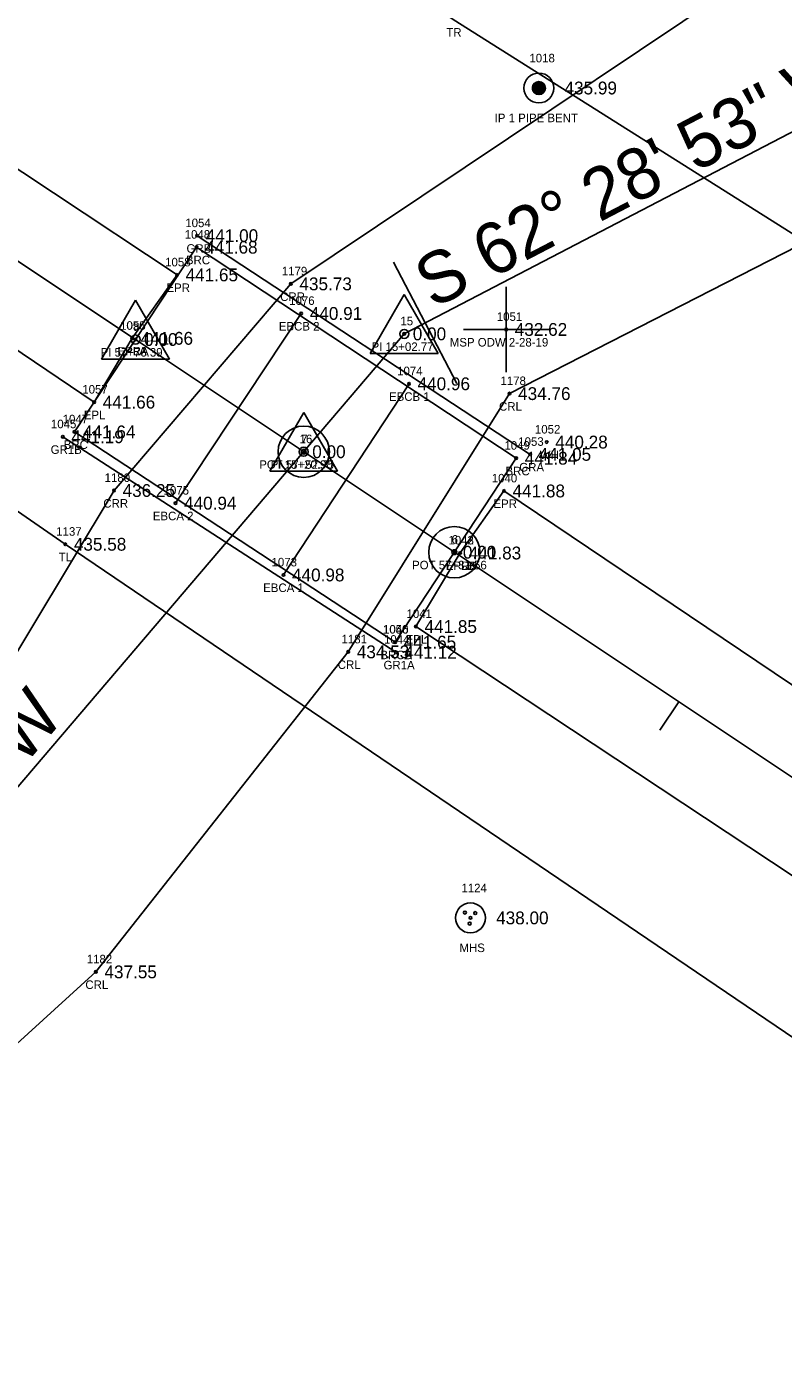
# Model space of a CAD drawing. Extents: x 1796360 to 1799195, y 895805 to 899730.
# Drawn here: x 1798350 to 1798438.5, y 896378.1 to 896534.1 of the extents above; entities that cross this region are included whole.
import ezdxf

# ---------------------------------------------------------------- set-up
doc = ezdxf.new("R2010")
doc.units = 0
for name, color, linetype in [('RD_EX_Bridge', 7, 'Continuous'), ('RD_EX_Bridge_txCode', 7, 'Continuous'), ('RD_EX_DR_Inlet', 7, 'Continuous'), ('RD_EX_DV_Prop_txCode', 7, 'Continuous'), ('RD_EX_DV_PropPin', 7, 'Continuous'), ('RD_EX_GuardRail', 7, 'Continuous'), ('RD_EX_GuardRail_txCode', 7, 'Continuous'), ('RD_EX_H2O', 7, 'Continuous'), ('RD_EX_H2O_txCode', 7, 'Continuous'), ('RD_EX_Misc_txCode', 7, 'Continuous'), ('RD_EX_Road', 7, 'Continuous'), ('RD_EX_Road_txCode', 7, 'Continuous'), ('RD_EX_SU_Misc_TxCode', 7, 'Continuous'), ('RD_EX_TX_Bridge_ELEV', 7, 'Continuous'), ('RD_EX_TX_DV_Prop_ELEV', 7, 'Continuous'), ('RD_EX_TX_GuardRail_ELEV', 7, 'Continuous'), ('RD_EX_TX_H2O_ELEV', 7, 'Continuous'), ('RD_EX_TX_Misc_ELEV', 7, 'Continuous'), ('RD_EX_TX_Road_ELEV', 7, 'Continuous'), ('RD_EX_TX_UT_ELEV', 7, 'Continuous'), ('RD_EX_TX_VEG_ELEV', 7, 'Continuous'), ('RD_EX_UT_txCode', 7, 'Continuous'), ('RD_EX_VEG', 7, 'Continuous'), ('RD_EX_VEG_txCode', 7, 'Continuous'), ('RD_HC_Cl', 7, 'Continuous'), ('RD_HC_Data', 7, 'Continuous'), ('RD_HC_Data_Tic', 7, 'Continuous'), ('RD_HC_Survey_ELEV', 7, 'Continuous'), ('RD_HC_txCode', 7, 'Continuous'), ('RD_SMD_Locator', 7, 'Continuous')]:
    doc.layers.add(name, color=color, linetype=linetype)

msp = doc.modelspace()

# ---------------------------------------------------------------- linework, layer by layer
at = {"layer": 'RD_EX_Bridge'}
for p, q in [((1798367.36, 896478.36), (1798382.07, 896500.56)), ((1798379.99, 896469.96), (1798394.68, 896492.33))]:
    msp.add_line(p, q, dxfattribs=at)
msp.add_lwpolyline([(1798393.06, 896462.1), (1798355.54, 896486.7), (1798369.83, 896508.31), (1798407.22, 896483.62), (1798393.06, 896462.1)], dxfattribs=at)
at = {"layer": 'RD_EX_DR_Inlet'}
for centre, radius in [((1798401.87, 896429.83), 1.75), ((1798401.21, 896430.46), 0.175), ((1798402.43, 896430.39), 0.175), ((1798401.78, 896429.17), 0.175)]:
    msp.add_circle(centre, radius, dxfattribs=at)
at = {"layer": 'RD_EX_DV_PropPin'}
for p, q in [((1798409.2, 896526.57), (1798409.2, 896527.31)), ((1798409.23, 896526.51), (1798409.23, 896527.36)), ((1798409.27, 896526.46), (1798409.27, 896527.41)), ((1798409.3, 896526.42), (1798409.3, 896527.45)), ((1798409.34, 896526.39), (1798409.34, 896527.49)), ((1798409.37, 896526.36), (1798409.37, 896527.52)), ((1798409.41, 896526.33), (1798409.41, 896527.55)), ((1798409.44, 896526.3), (1798409.44, 896527.57)), ((1798409.48, 896526.28), (1798409.48, 896527.59)), ((1798409.51, 896526.26), (1798409.51, 896527.61)), ((1798409.55, 896526.25), (1798409.55, 896527.63)), ((1798409.58, 896526.23), (1798409.58, 896527.65)), ((1798409.62, 896526.22), (1798409.62, 896527.66)), ((1798409.65, 896526.21), (1798409.65, 896527.67)), ((1798409.69, 896526.2), (1798409.69, 896527.68)), ((1798409.73, 896526.19), (1798409.73, 896527.69)), ((1798409.76, 896526.18), (1798409.76, 896527.69)), ((1798409.8, 896526.18), (1798409.8, 896527.7)), ((1798409.83, 896526.18), (1798409.83, 896527.7)), ((1798409.87, 896526.18), (1798409.87, 896527.7)), ((1798409.9, 896526.18), (1798409.9, 896527.7)), ((1798409.94, 896526.18), (1798409.94, 896527.7)), ((1798409.97, 896526.18), (1798409.97, 896527.69)), ((1798410.01, 896526.19), (1798410.01, 896527.69)), ((1798410.04, 896526.2), (1798410.04, 896527.68)), ((1798410.08, 896526.21), (1798410.08, 896527.67)), ((1798410.11, 896526.22), (1798410.11, 896527.66)), ((1798410.15, 896526.23), (1798410.15, 896527.65)), ((1798410.18, 896526.25), (1798410.18, 896527.63)), ((1798410.22, 896526.26), (1798410.22, 896527.61)), ((1798410.25, 896526.28), (1798410.25, 896527.59)), ((1798410.29, 896526.3), (1798410.29, 896527.57)), ((1798410.32, 896526.33), (1798410.32, 896527.55)), ((1798410.36, 896526.36), (1798410.36, 896527.52)), ((1798410.39, 896526.39), (1798410.39, 896527.49)), ((1798410.43, 896526.42), (1798410.43, 896527.45)), ((1798410.46, 896526.46), (1798410.46, 896527.41)), ((1798410.5, 896526.51), (1798410.5, 896527.36)), ((1798410.53, 896526.57), (1798410.53, 896527.31)), ((1798409.13, 896526.74), (1798409.13, 896527.13)), ((1798409.16, 896526.64), (1798409.16, 896527.24)), ((1798410.57, 896526.64), (1798410.57, 896527.24)), ((1798410.6, 896526.74), (1798410.6, 896527.13))]:
    msp.add_line(p, q, dxfattribs=at)
for radius in [1.75, 0.761]:
    msp.add_circle((1798409.87, 896526.94), radius, dxfattribs=at)
at = {"layer": 'RD_EX_GuardRail'}
for p, q in [((1798408.85, 896484.07), (1798369.9, 896509.66)), ((1798393.13, 896460.91), (1798354.18, 896486.13))]:
    msp.add_line(p, q, dxfattribs=at)
at = {"layer": 'RD_EX_H2O'}
for p, q in [((1798406.05, 896493.69), (1798406.05, 896503.69)), ((1798401.05, 896498.69), (1798411.05, 896498.69))]:
    msp.add_line(p, q, dxfattribs=at)
for points in [[(1798502.61, 896635.66), (1798452.16, 896551.79), (1798380.86, 896504.02), (1798360.17, 896479.84), (1798335.44, 896438.68), (1798277.37, 896387.2), (1798228.36, 896339.61), (1798175.66, 896278.7), (1798083.83, 896204.11), (1798020.11, 896146.19)], [(1798443.56, 896510.19), (1798406.44, 896491.18), (1798387.57, 896460.96), (1798358.05, 896423.51), (1798298.17, 896368.97), (1798249.86, 896318.72)]]:
    msp.add_lwpolyline(points, dxfattribs=at)
msp.add_circle((1798406.05, 896498.69), 0.15, dxfattribs=at)
at = {"layer": 'RD_EX_Road'}
for points in [[(1798362.28, 896497.65), (1798367.54, 896505.07), (1798280.71, 896562.69), (1798193.2, 896621.02), (1798104.98, 896679.23), (1798017.88, 896737.39), (1797930.72, 896795.63), (1797844.07, 896853.07), (1797758.11, 896906.97)], [(1798362.28, 896497.65), (1798357.85, 896490.18), (1798271.29, 896548.71), (1798183.2, 896606.17), (1798096.06, 896663.44), (1798006.57, 896721.75), (1797920.8, 896779.27), (1797834.41, 896836.87), (1797748.77, 896891.01)], [(1799016.83, 896078.37), (1798931.94, 896134.3), (1798843.73, 896191.67), (1798753.3, 896249.87), (1798664.51, 896307.9), (1798573.47, 896367.69), (1798486.82, 896425.22), (1798405.79, 896479.79), (1798400.67, 896472.53)], [(1799005.77, 896063.27), (1798987.67, 896075.09), (1798974.89, 896083.47), (1798920.67, 896119.42), (1798834.47, 896175.11), (1798832.16, 896176.64), (1798822.63, 896182.83), (1798742.86, 896234.39), (1798653.4, 896292.37), (1798563.64, 896351.71), (1798476.02, 896410.61), (1798395.49, 896463.92), (1798400.67, 896472.53)]]:
    msp.add_lwpolyline(points, dxfattribs=at)
at = {"layer": 'RD_EX_SU_Misc_TxCode'}
msp.add_circle((1798410.79, 896485.51), 0.15, dxfattribs=at)
at = {"layer": 'RD_EX_VEG'}
for points in [[(1799022.27, 896088.33), (1798937.86, 896144.41), (1798896.41, 896211.5), (1798869.11, 896228.04), (1798778.26, 896284.04), (1798691.36, 896345.52), (1798595.8, 896403.96), (1798518.88, 896459.81), (1798399.83, 896534.95), (1798299.84, 896602.99), (1798218.96, 896659.85), (1798132.31, 896718.94), (1798044.28, 896770.93), (1797952.52, 896827.83), (1797861.07, 896893.41), (1797773.58, 896947.34)], [(1798749.58, 896161.12), (1798777.44, 896196.37), (1798732.29, 896222.81), (1798646.22, 896279.46), (1798558.62, 896342.53), (1798466.43, 896397.6), (1798354.47, 896473.55), (1798259.03, 896539.65), (1798173.88, 896596.34), (1798087.56, 896652.32), (1797997.75, 896711.89), (1797914.4, 896770.94), (1797832.15, 896824.19), (1797742.8, 896880.21)]]:
    msp.add_lwpolyline(points, dxfattribs=at)
at = {"layer": 'RD_HC_Cl'}
for p, q in [((1798362.69, 896497.51), (1798188.2, 896613.6)), ((1798452.47, 896528.57), (1798394.12, 896498.17)), ((1798394.12, 896498.17), (1798280.52, 896365)), ((1798659.28, 896299.6), (1798362.69, 896497.51))]:
    msp.add_line(p, q, dxfattribs=at)
at = {"layer": 'RD_HC_Data'}
for p, q in [((1798390.15, 896495.88), (1798394.12, 896502.76)), ((1798394.12, 896502.76), (1798398.09, 896495.88)), ((1798358.71, 896495.22), (1798362.69, 896502.1)), ((1798362.69, 896502.1), (1798366.66, 896495.22)), ((1798358.71, 896495.22), (1798366.66, 896495.22)), ((1798390.15, 896495.88), (1798398.09, 896495.88)), ((1798378.39, 896482.09), (1798382.36, 896488.97)), ((1798382.36, 896488.97), (1798386.33, 896482.09)), ((1798378.39, 896482.09), (1798386.33, 896482.09))]:
    msp.add_line(p, q, dxfattribs=at)
for centre, radius in [((1798362.69, 896497.51), 0.529), ((1798394.12, 896498.17), 0.529), ((1798382.36, 896484.38), 3), ((1798382.36, 896484.38), 0.529), ((1798382.36, 896484.38), 0.282), ((1798399.98, 896472.62), 3), ((1798399.98, 896472.62), 0.282)]:
    msp.add_circle(centre, radius, dxfattribs=at)
at = {"layer": 'RD_HC_Data_Tic'}
for p, q in [((1798396.58, 896499.45), (1798392.88, 896506.55)), ((1798396.58, 896499.45), (1798400.27, 896492.36)), ((1798426.23, 896455.11), (1798424.01, 896451.78))]:
    msp.add_line(p, q, dxfattribs=at)
at = {"layer": 'RD_SMD_Locator'}
for centre in [(1798409.87, 896526.94), (1798369.9, 896509.66), (1798369.83, 896508.31), (1798367.54, 896505.07), (1798380.86, 896504.02), (1798382.07, 896500.56), (1798362.28, 896497.65), (1798362.28, 896497.65), (1798362.69, 896497.51), (1798394.12, 896498.17), (1798394.68, 896492.33), (1798357.85, 896490.18), (1798406.44, 896491.18), (1798355.54, 896486.7), (1798354.18, 896486.13), (1798382.36, 896484.38), (1798382.36, 896484.38), (1798407.22, 896483.62), (1798408.85, 896484.07), (1798360.17, 896479.84), (1798405.79, 896479.79), (1798367.36, 896478.36), (1798354.47, 896473.55), (1798399.98, 896472.62), (1798400.67, 896472.53), (1798400.67, 896472.53), (1798379.99, 896469.96), (1798395.49, 896463.92), (1798393.06, 896462.1), (1798393.06, 896462.1), (1798387.57, 896460.96), (1798393.13, 896460.91), (1798401.87, 896429.83), (1798358.05, 896423.51)]:
    msp.add_circle(centre, 0.15, dxfattribs=at)

# ---------------------------------------------------------------- texts
at = {"layer": 'RD_EX_Bridge_txCode'}
for s, p in [('1048', (1798368.44, 896509.31)), ('BRC', (1798368.58, 896506.31)), ('1076', (1798380.66, 896501.56)), ('EBCB 2', (1798379.45, 896498.56)), ('1074', (1798393.29, 896493.33)), ('EBCB 1', (1798392.34, 896490.33)), ('1047', (1798354.16, 896487.7)), ('BRC', (1798354.29, 896484.7)), ('1049', (1798405.84, 896484.62)), ('BRC', (1798405.97, 896481.62)), ('1075', (1798365.97, 896479.36)), ('EBCA 2', (1798364.71, 896476.36)), ('1073', (1798378.6, 896470.96)), ('EBCA 1', (1798377.62, 896467.96)), ('1050', (1798391.63, 896463.1)), ('1046', (1798391.65, 896463.1)), ('BRCA', (1798391.32, 896460.1)), ('BRCB', (1798391.33, 896460.1))]:
    msp.add_text(s, height=1, dxfattribs=at).set_placement(p)
at = {"layer": 'RD_EX_DV_Prop_txCode'}
for s, p in [('1018', (1798408.76, 896529.94)), ('IP 1 PIPE BENT', (1798404.7, 896522.94))]:
    msp.add_text(s, height=1, dxfattribs=at).set_placement(p)
at = {"layer": 'RD_EX_GuardRail_txCode'}
for s, p in [('1054', (1798368.51, 896510.66)), ('GRB', (1798368.65, 896507.66)), ('1045', (1798352.79, 896487.13)), ('GR1B', (1798352.76, 896484.13)), ('1053', (1798407.46, 896485.07)), ('GRA', (1798407.58, 896482.07)), ('1044', (1798391.75, 896461.91)), ('GR1A', (1798391.7, 896458.91))]:
    msp.add_text(s, height=1, dxfattribs=at).set_placement(p)
at = {"layer": 'RD_EX_H2O_txCode'}
for s, p in [('1179', (1798379.8, 896505.02)), ('CRR', (1798379.61, 896502.02)), ('1178', (1798405.38, 896492.18)), ('CRL', (1798405.21, 896489.18)), ('1180', (1798359.07, 896480.84)), ('CRR', (1798358.92, 896477.84)), ('1181', (1798386.79, 896461.96)), ('CRL', (1798386.34, 896458.96)), ('1182', (1798356.98, 896424.51)), ('CRL', (1798356.82, 896421.51))]:
    msp.add_text(s, height=1, dxfattribs=at).set_placement(p)
at = {"layer": 'RD_EX_Misc_txCode'}
for s, p in [('1051', (1798404.95, 896499.69)), ('MSP ODW 2-28-19', (1798399.45, 896496.69)), ('1052', (1798409.41, 896486.51)), ('WH', (1798409.98, 896483.51))]:
    msp.add_text(s, height=1, dxfattribs=at).set_placement(p)
at = {"layer": 'RD_EX_Road_txCode'}
for s, p in [('1058', (1798366.15, 896506.07)), ('EPR', (1798366.31, 896503.07)), ('1056', (1798360.87, 896498.65)), ('1055', (1798360.9, 896498.65)), ('EPRA', (1798360.57, 896495.65)), ('EPLA', (1798360.59, 896495.65)), ('1057', (1798356.46, 896491.18)), ('EPL', (1798356.64, 896488.18)), ('1040', (1798404.36, 896480.79)), ('EPR', (1798404.56, 896477.79)), ('1042', (1798399.29, 896473.53)), ('1043', (1798399.29, 896473.53)), ('EPRB', (1798398.97, 896470.53)), ('EPLB', (1798398.99, 896470.53)), ('1041', (1798394.39, 896464.92)), ('EPL', (1798394.28, 896461.92))]:
    msp.add_text(s, height=1, dxfattribs=at).set_placement(p)
at = {"layer": 'RD_EX_TX_Bridge_ELEV'}
for s, p in [('441.68', (1798370.83, 896507.56)), ('440.91', (1798383.07, 896499.81)), ('440.96', (1798395.68, 896491.58)), ('441.64', (1798356.54, 896485.95)), ('441.84', (1798408.22, 896482.87)), ('440.94', (1798368.36, 896477.61)), ('440.98', (1798380.99, 896469.21)), ('441.65', (1798394.06, 896461.35)), ('441.65', (1798394.06, 896461.35))]:
    msp.add_text(s, height=1.5, dxfattribs=at).set_placement(p)
at = {"layer": 'RD_EX_TX_DV_Prop_ELEV'}
msp.add_text('435.99', height=1.5, dxfattribs=at).set_placement((1798412.87, 896526.19))
at = {"layer": 'RD_EX_TX_GuardRail_ELEV'}
for s, p in [('441.00', (1798370.9, 896508.91)), ('441.19', (1798355.18, 896485.38)), ('441.05', (1798409.85, 896483.32)), ('441.12', (1798394.13, 896460.16))]:
    msp.add_text(s, height=1.5, dxfattribs=at).set_placement(p)
at = {"layer": 'RD_EX_TX_H2O_ELEV'}
for s, p in [('435.73', (1798381.86, 896503.27)), ('434.76', (1798407.44, 896490.43)), ('436.25', (1798361.17, 896479.09)), ('434.53', (1798388.57, 896460.21)), ('437.55', (1798359.05, 896422.76))]:
    msp.add_text(s, height=1.5, dxfattribs=at).set_placement(p)
at = {"layer": 'RD_EX_TX_Misc_ELEV'}
for s, p in [('432.62', (1798407.05, 896497.94)), ('440.28', (1798411.79, 896484.76))]:
    msp.add_text(s, height=1.5, dxfattribs=at).set_placement(p)
at = {"layer": 'RD_EX_TX_Road_ELEV'}
for s, p in [('441.65', (1798368.54, 896504.32)), ('441.66', (1798363.28, 896496.9)), ('441.66', (1798363.28, 896496.9)), ('441.66', (1798358.85, 896489.43)), ('441.88', (1798406.79, 896479.04)), ('441.83', (1798401.67, 896471.78)), ('441.83', (1798401.67, 896471.78)), ('441.85', (1798396.49, 896463.17))]:
    msp.add_text(s, height=1.5, dxfattribs=at).set_placement(p)
at = {"layer": 'RD_EX_TX_UT_ELEV'}
msp.add_text('438.00', height=1.5, dxfattribs=at).set_placement((1798404.87, 896429.08))
at = {"layer": 'RD_EX_TX_VEG_ELEV'}
msp.add_text('435.58', height=1.5, dxfattribs=at).set_placement((1798355.47, 896472.8))
at = {"layer": 'RD_EX_UT_txCode'}
for s, p in [('1124', (1798400.81, 896432.83)), ('MHS', (1798400.58, 896425.83))]:
    msp.add_text(s, height=1, dxfattribs=at).set_placement(p)
at = {"layer": 'RD_EX_VEG_txCode'}
for s, p in [('TR', (1798399.04, 896532.95)), ('1137', (1798353.41, 896474.55)), ('TL', (1798353.7, 896471.55))]:
    msp.add_text(s, height=1, dxfattribs=at).set_placement(p)
at = {"layer": 'RD_HC_Data'}
for s, rotation, p in [('S 62%%d 28\' 53" W', 27.5186, (1798397.48, 896501.05)), ('S 40%%d 27\' 57" W', 49.5342, (1798318.01, 896410.49))]:
    msp.add_text(s, height=6, rotation=rotation, dxfattribs=at).set_placement(p)
at = {"layer": 'RD_HC_Survey_ELEV'}
for p in [(1798363.69, 896496.76), (1798395.12, 896497.42), (1798383.36, 896483.63), (1798383.36, 896483.63), (1798400.98, 896471.87)]:
    msp.add_text('0.00', height=1.5, dxfattribs=at).set_placement(p)
at = {"layer": 'RD_HC_txCode'}
for s, p in [('8', (1798362.4, 896498.51)), ('15', (1798393.67, 896499.17)), ('PI 57+76.39', (1798358.6, 896495.51)), ('PI 15+02.77', (1798390.3, 896496.17)), ('16', (1798381.88, 896485.38)), ('7', (1798382.07, 896485.38)), ('POT 57+52.75', (1798377.16, 896482.38)), ('PI 15+20.90', (1798378.5, 896482.38)), ('6', (1798399.67, 896473.62)), ('POT 57+31.56', (1798395.04, 896470.62))]:
    msp.add_text(s, height=1, dxfattribs=at).set_placement(p)

doc.saveas('drawing.dxf')
